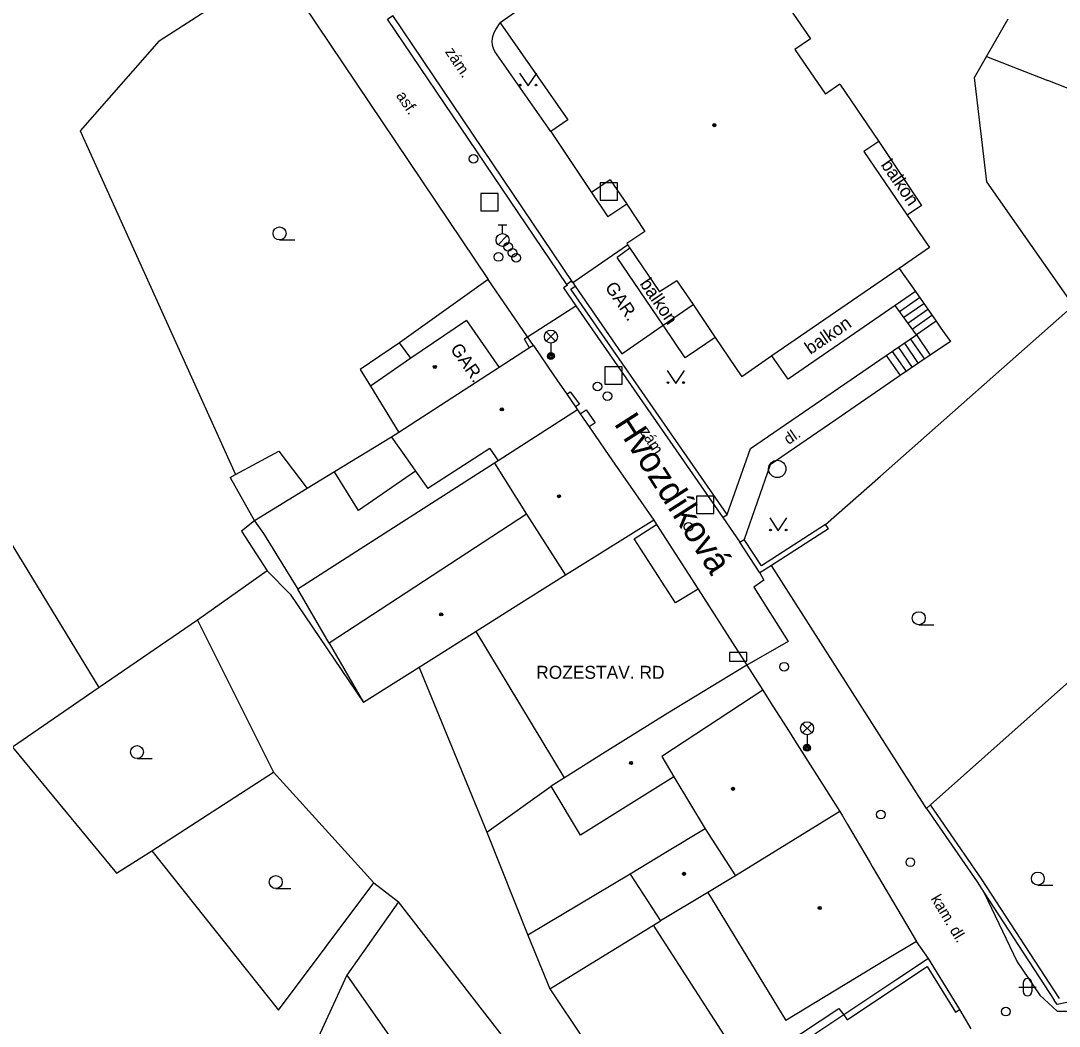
# Model space of a CAD drawing. Extents: x -598233 to -596890, y -1157848 to -1156431.
# Drawn here: x -597463.2 to -597403.3, y -1157373.5 to -1157315.5 of the extents above; entities that cross this region are included whole.
import ezdxf

# ---------------------------------------------------------------- set-up
doc = ezdxf.new("R2010")
doc.units = 0
for name, color, linetype in [('Level 11', 7, 'Continuous'), ('Level 24', 7, 'Continuous'), ('Level 26', 7, 'Continuous'), ('Level 27', 7, 'Continuous'), ('Level 28', 7, 'Continuous'), ('Level 33', 7, 'Continuous'), ('Level 36', 7, 'Continuous'), ('Level 39', 7, 'Continuous'), ('Level 40', 7, 'Continuous'), ('Level 41', 7, 'Continuous'), ('Level 42', 7, 'Continuous'), ('Level 5', 7, 'Continuous'), ('Level 50', 7, 'Continuous'), ('Level 7', 7, 'Continuous'), ('Level 8', 7, 'Continuous')]:
    doc.layers.add(name, color=color, linetype=linetype)

msp = doc.modelspace()

# ---------------------------------------------------------------- linework, layer by layer
at = {"layer": 'Level 11'}
for points in [[(-597431.38, -1157330.61), (-597441.77, -1157315.21)], [(-597407.49, -1157317.56), (-597406.25, -1157315.39)], [(-597432.64, -1157321.89), (-597435.88, -1157317.27), (-597435.95, -1157317.1), (-597436, -1157316.91), (-597436.02, -1157316.68), (-597435.99, -1157316.41), (-597435.92, -1157316.18), (-597435.82, -1157316), (-597435.57, -1157315.62)], [(-597455.25, -1157316.66), (-597459.82, -1157321.86), (-597450.85, -1157341.7)], [(-597407.48, -1157324.81), (-597408.18, -1157318.78), (-597407.49, -1157317.56)], [(-597407.49, -1157317.56), (-597403.95, -1157318.95)], [(-597458.72, -1157354), (-597478.57, -1157321.39), (-597481.79, -1157323.51), (-597492.54, -1157318.68), (-597503.21, -1157320.29), (-597510.41, -1157323.17)], [(-597394.15, -1157322.81), (-597403.95, -1157318.95)], [(-597413.7, -1157322.4699), (-597411.24, -1157326.1599), (-597412.07, -1157326.73)], [(-597402.48, -1157331.95), (-597407.48, -1157324.81)], [(-597430.3, -1157325.41), (-597429.35, -1157326.83)], [(-597428.26, -1157326.1), (-597429.35, -1157326.83)], [(-597428.08, -1157328.63), (-597428.81, -1157329.17)], [(-597426.15, -1157333.08), (-597428.81, -1157329.17)], [(-597412.54, -1157329.8), (-597411.6, -1157331.14)], [(-597436.26, -1157330.44), (-597441.37, -1157334.09)], [(-597411.6, -1157331.14), (-597412.76, -1157331.94)], [(-597412.52, -1157332.28), (-597411.36, -1157331.48)], [(-597411.6, -1157331.14), (-597410.4, -1157332.84)], [(-597433.99, -1157333.75), (-597431.19, -1157331.96)], [(-597426.15, -1157333.08), (-597424.43, -1157331.89)], [(-597412.76, -1157331.94), (-597418.95, -1157336.2), (-597419.88, -1157334.85)], [(-597411.54, -1157333.64), (-597412.76, -1157331.94)], [(-597412.27, -1157332.62), (-597411.12, -1157331.82)], [(-597412.03, -1157332.96), (-597410.88, -1157332.1599)], [(-597411.78, -1157333.3), (-597410.64, -1157332.5)], [(-597410.4, -1157332.84), (-597411.54, -1157333.64)], [(-597410.4, -1157332.84), (-597410.13, -1157333.24), (-597409.93, -1157333.52), (-597409.58, -1157334.01), (-597410.74, -1157334.81)], [(-597428.54, -1157334.73), (-597426.15, -1157333.08)], [(-597423.15, -1157333.79), (-597424.18, -1157334.49), (-597424.88, -1157334.96), (-597426.15, -1157333.08)], [(-597441.37, -1157334.09), (-597443.65, -1157335.64), (-597443.06, -1157336.6)], [(-597440.7199, -1157334.99), (-597441.37, -1157334.09)], [(-597413.28, -1157334.83), (-597411.54, -1157333.64)], [(-597412.23, -1157334.12), (-597411.43, -1157335.28)], [(-597411.88, -1157333.88), (-597411.08, -1157335.04)], [(-597411.54, -1157333.64), (-597410.74, -1157334.81)], [(-597412.93, -1157334.59), (-597412.12, -1157335.76)], [(-597412.58, -1157334.36), (-597411.78, -1157335.52)], [(-597422.47, -1157344), (-597421.11, -1157340.2), (-597413.28, -1157334.83)], [(-597413.28, -1157334.83), (-597412.4699, -1157335.99)], [(-597410.74, -1157334.81), (-597412.4699, -1157335.99)], [(-597412.4699, -1157335.99), (-597416.19, -1157338.54), (-597419.99, -1157341.14), (-597421.48, -1157345.45)], [(-597431.7199, -1157337.06), (-597431.52, -1157336.92), (-597430.99, -1157337.64), (-597431.21, -1157337.79)], [(-597430.94, -1157338.2), (-597430.61, -1157337.9699), (-597430.09, -1157338.7199), (-597430.43, -1157338.95)], [(-597441.84, -1157339.54), (-597445.13, -1157341.55), (-597446.7, -1157342.51)], [(-597451.15, -1157341.86), (-597450.85, -1157341.7), (-597448.34, -1157340.35), (-597446.7, -1157342.51)], [(-597435.9, -1157341.05), (-597444.39, -1157346.49)], [(-597451.15, -1157341.86), (-597449.74, -1157344.37)], [(-597440.45, -1157341.51), (-597443.75, -1157343.77), (-597445.13, -1157341.55)], [(-597446.7, -1157342.51), (-597449.74, -1157344.37)], [(-597449.74, -1157344.37), (-597450.49, -1157344.96), (-597449.02, -1157347.25)], [(-597449.74, -1157344.37), (-597449.2199, -1157345.11)], [(-597416.62, -1157344.84), (-597416.78, -1157344.58)], [(-597449.2199, -1157345.11), (-597447.24, -1157348.32)], [(-597444.39, -1157346.49), (-597447.24, -1157348.32)], [(-597449.02, -1157347.25), (-597453.04, -1157350.1)], [(-597449.02, -1157347.25), (-597447.69, -1157348.61)], [(-597420.57, -1157347.37), (-597420.34, -1157347.79), (-597420.92, -1157348.2)], [(-597445.44, -1157351.43), (-597447.24, -1157348.32)], [(-597420.92, -1157348.2), (-597418.95, -1157351.34), (-597421.33, -1157352.7)], [(-597447.69, -1157348.61), (-597443.46, -1157354.86)], [(-597453.04, -1157350.1), (-597458.72, -1157354), (-597463.71, -1157357.43), (-597457.7199, -1157364.71), (-597455.68, -1157363.4099)], [(-597453.04, -1157350.1), (-597448.65, -1157358.87)], [(-597431.86, -1157359.21), (-597436.96, -1157350.76)], [(-597455.68, -1157363.4099), (-597448.65, -1157358.87)], [(-597448.65, -1157358.87), (-597442.86, -1157365.27)], [(-597436.34, -1157362.34), (-597433.9699, -1157368.28)], [(-597455.68, -1157363.4099), (-597448.36, -1157372.62), (-597442.86, -1157365.27)], [(-597442.86, -1157365.27), (-597441.43, -1157366.36)], [(-597428.07, -1157364.76), (-597433.9699, -1157368.28)], [(-597407.62, -1157365.85), (-597405.72, -1157369.82), (-597404.41, -1157371.75), (-597403.42, -1157372.68), (-597402.25, -1157372.68), (-597401.32, -1157372.58), (-597400.2, -1157372.49), (-597398.82, -1157371.76)], [(-597441.43, -1157366.36), (-597444.4099, -1157370.59)], [(-597430.73, -1157380.1599), (-597441.43, -1157366.36)], [(-597426.7199, -1157367.71), (-597426.31, -1157367.46)], [(-597433.9699, -1157368.28), (-597432.7, -1157371.39)], [(-597432.7, -1157371.39), (-597426.7199, -1157367.71)], [(-597421.35, -1157376.04), (-597426.7199, -1157367.71)], [(-597444.4099, -1157370.59), (-597447.7, -1157377.75)], [(-597444.4099, -1157370.59), (-597435.63, -1157383.17)], [(-597432.7, -1157371.39), (-597426.76, -1157380.28)]]:
    msp.add_lwpolyline(points, dxfattribs=at)
at = {"layer": 'Level 24'}
for points in [[(-597433.99, -1157333.75), (-597434.17, -1157333.88)], [(-597433.87, -1157334.38), (-597434.17, -1157333.88)]]:
    msp.add_lwpolyline(points, dxfattribs=at)
msp.add_lwpolyline([(-597422.32, -1157352.47), (-597421.32, -1157352.47), (-597421.32, -1157351.97), (-597422.32, -1157351.97)], close=True, dxfattribs=at)
at = {"layer": 'Level 26'}
for points in [[(-597429.8, -1157325.86), (-597428.8, -1157325.86), (-597428.8, -1157324.86), (-597429.8, -1157324.86)], [(-597436.69, -1157326.48), (-597435.69, -1157326.48), (-597435.69, -1157325.48), (-597436.69, -1157325.48)], [(-597429.52, -1157336.48), (-597428.52, -1157336.48), (-597428.52, -1157335.48), (-597429.52, -1157335.48)], [(-597424.24, -1157343.95), (-597423.24, -1157343.95), (-597423.24, -1157342.95), (-597424.24, -1157342.95)]]:
    msp.add_lwpolyline(points, close=True, dxfattribs=at)
at = {"layer": 'Level 27'}
msp.add_circle((-597419.57, -1157341.37), 0.5, dxfattribs=at)
at = {"layer": 'Level 28'}
for p, q in [((-597435.68, -1157327.285), (-597435.18, -1157327.285)), ((-597435.43, -1157327.785), (-597435.43, -1157327.285)), ((-597435.688, -1157328.432), (-597435.158, -1157327.902))]:
    msp.add_line(p, q, dxfattribs=at)
for centre, radius in [((-597437.11, -1157323.47), 0.25), ((-597435.43, -1157328.16), 0.375), ((-597435.11, -1157328.55), 0.25), ((-597434.85, -1157328.9), 0.25), ((-597435.67, -1157329.14), 0.25), ((-597434.64, -1157329.19), 0.25), ((-597429.95, -1157336.62), 0.25), ((-597429.38, -1157337.18), 0.25), ((-597424.7, -1157344.72), 0.25), ((-597419.18, -1157352.79), 0.25), ((-597413.59, -1157361.33), 0.25), ((-597411.89, -1157364.08), 0.25), ((-597406.38, -1157372.7), 0.25)]:
    msp.add_circle(centre, radius, dxfattribs=at)
at = {"layer": 'Level 33'}
for p, q in [((-597432.905, -1157334), (-597432.375, -1157333.47)), ((-597432.905, -1157333.47), (-597432.375, -1157334)), ((-597432.64, -1157334.11), (-597432.64, -1157334.86)), ((-597418.115, -1157356.61), (-597417.585, -1157356.08)), ((-597418.115, -1157356.08), (-597417.585, -1157356.61)), ((-597417.85, -1157356.72), (-597417.85, -1157357.47))]:
    msp.add_line(p, q, dxfattribs=at)
for centre, radius in [((-597432.64, -1157333.735), 0.375), ((-597432.64, -1157334.86), 0.2), ((-597432.64, -1157334.86), 0.1445), ((-597432.64, -1157334.86), 0.0876), ((-597417.85, -1157356.345), 0.375), ((-597417.85, -1157357.47), 0.2), ((-597417.85, -1157357.47), 0.1445), ((-597417.85, -1157357.47), 0.0876)]:
    msp.add_circle(centre, radius, dxfattribs=at)
at = {"layer": 'Level 36'}
for p, q in [((-597448.3, -1157328.155), (-597447.425, -1157328.155)), ((-597411.4, -1157350.365), (-597410.525, -1157350.365)), ((-597456.53, -1157358.0949), (-597455.655, -1157358.0949)), ((-597448.52, -1157365.5949), (-597447.645, -1157365.5949)), ((-597404.53, -1157365.395), (-597403.655, -1157365.395)), ((-597405.626, -1157371.296), (-597404.626, -1157371.296)), ((-597405.376, -1157371.046), (-597405.376, -1157371.546)), ((-597404.876, -1157371.046), (-597404.876, -1157371.546))]:
    msp.add_line(p, q, dxfattribs=at)
for points in [[(-597434.45, -1157318.52), (-597433.95, -1157319.27), (-597433.45, -1157318.52)], [(-597425.93, -1157335.69), (-597425.43, -1157336.44), (-597424.93, -1157335.69)], [(-597420.01, -1157344.2), (-597419.51, -1157344.95), (-597419.01, -1157344.2)]]:
    msp.add_lwpolyline(points, dxfattribs=at)
for centre, radius in [((-597434.4002, -1157319.2198), 0.05), ((-597433.5008, -1157319.2198), 0.05), ((-597448.3001, -1157327.7799), 0.375), ((-597425.8802, -1157336.3898), 0.05), ((-597424.9808, -1157336.3898), 0.05), ((-597419.9602, -1157344.8998), 0.05), ((-597419.0608, -1157344.8998), 0.05), ((-597411.4001, -1157349.9899), 0.375), ((-597456.5301, -1157357.7198), 0.375), ((-597404.5301, -1157365.0199), 0.375), ((-597448.5201, -1157365.2198), 0.375)]:
    msp.add_circle(centre, radius, dxfattribs=at)
for centre, start, end in [((-597405.1257, -1157371.0463), 0, 180), ((-597405.1257, -1157371.5463), 180, 0)]:
    msp.add_arc(centre, 0.25, start, end, dxfattribs=at)
at = {"layer": 'Level 39'}
for centre, radius in [((-597423.21, -1157321.53), 0.09), ((-597423.21, -1157321.53), 0.0398), ((-597439.34, -1157335.49), 0.09), ((-597439.34, -1157335.49), 0.0398), ((-597435.4699, -1157337.94), 0.09), ((-597435.4699, -1157337.94), 0.0398), ((-597432.17, -1157342.95), 0.09), ((-597432.17, -1157342.95), 0.0398), ((-597438.9699, -1157349.77), 0.09), ((-597438.9699, -1157349.77), 0.0398), ((-597428.01, -1157358.35), 0.09), ((-597428.01, -1157358.35), 0.0398), ((-597422.13, -1157359.84), 0.09), ((-597422.13, -1157359.84), 0.0398), ((-597424.96, -1157364.75), 0.09), ((-597424.96, -1157364.75), 0.0398), ((-597417.12, -1157366.7199), 0.09), ((-597417.12, -1157366.7199), 0.0398)]:
    msp.add_circle(centre, radius, dxfattribs=at)
at = {"layer": 'Level 5'}
for points in [[(-597420.01, -1157313.12), (-597417.6599, -1157316.54)], [(-597433.82, -1157314.43), (-597434.48, -1157314.88), (-597435.57, -1157315.62)], [(-597435.57, -1157315.62), (-597431.6599, -1157321.23)], [(-597417.6599, -1157316.54), (-597418.56, -1157317.1599)], [(-597418.56, -1157317.1599), (-597416.79, -1157319.74)], [(-597415.96, -1157319.17), (-597416.79, -1157319.74)], [(-597415.96, -1157319.17), (-597413.7, -1157322.4699)], [(-597431.6599, -1157321.23), (-597432.64, -1157321.89)], [(-597432.64, -1157321.89), (-597430.3, -1157325.4099)], [(-597413.7, -1157322.4699), (-597414.57, -1157323.06)], [(-597414.57, -1157323.06), (-597412.07, -1157326.73)], [(-597429.21, -1157324.68), (-597430.3, -1157325.4099)], [(-597429.21, -1157324.68), (-597428.62, -1157325.56), (-597428.28, -1157326.06), (-597428.26, -1157326.1), (-597427.21, -1157327.67)], [(-597412.07, -1157326.73), (-597410.79, -1157328.6)], [(-597427.21, -1157327.67), (-597428.26, -1157328.37)], [(-597431.38, -1157330.61), (-597428.21, -1157328.44)], [(-597428.26, -1157328.37), (-597428.21, -1157328.44), (-597428.08, -1157328.63)], [(-597428.08, -1157328.63), (-597426.37, -1157331.15)], [(-597410.79, -1157328.6), (-597412.54, -1157329.8)], [(-597412.54, -1157329.8), (-597419.88, -1157334.85)], [(-597425.36, -1157330.51), (-597426.37, -1157331.15)], [(-597425.36, -1157330.51), (-597424.43, -1157331.89), (-597423.15, -1157333.79)], [(-597431.38, -1157330.61), (-597431.24, -1157330.82), (-597428.54, -1157334.73)], [(-597437.51, -1157332.8), (-597440.7199, -1157334.99)], [(-597437.51, -1157332.8), (-597435.63, -1157335.52)], [(-597423.15, -1157333.79), (-597421.62, -1157336.05)], [(-597433.65, -1157334.24), (-597433.87, -1157334.38), (-597435.63, -1157335.52)], [(-597433.65, -1157334.24), (-597432.46, -1157335.98), (-597432.12, -1157336.48), (-597431.76, -1157337), (-597431.7199, -1157337.06)], [(-597440.7199, -1157334.99), (-597443.06, -1157336.6)], [(-597419.88, -1157334.85), (-597421.62, -1157336.05)], [(-597435.63, -1157335.52), (-597441.42, -1157339.28)], [(-597443.06, -1157336.6), (-597441.42, -1157339.28)], [(-597431.7199, -1157337.06), (-597431.21, -1157337.79)], [(-597431.1, -1157337.96), (-597435.68, -1157340.9)], [(-597431.21, -1157337.79), (-597431.1, -1157337.96)], [(-597431.1, -1157337.96), (-597430.94, -1157338.2)], [(-597430.94, -1157338.2), (-597430.43, -1157338.95)], [(-597441.42, -1157339.28), (-597441.84, -1157339.54)], [(-597430.43, -1157338.95), (-597430.09, -1157339.44), (-597429.29, -1157340.6), (-597428.95, -1157341.09), (-597426.7, -1157344.34)], [(-597441.84, -1157339.54), (-597440.9, -1157340.87)], [(-597436.1599, -1157340.19), (-597439.74, -1157342.51)], [(-597436.1599, -1157340.19), (-597435.68, -1157340.9)], [(-597440.9, -1157340.87), (-597440.45, -1157341.51), (-597439.74, -1157342.51)], [(-597435.68, -1157340.9), (-597435.9, -1157341.05)], [(-597435.9, -1157341.05), (-597434.04, -1157343.98)], [(-597434.04, -1157343.98), (-597445.44, -1157351.43)], [(-597434.04, -1157343.98), (-597431.79, -1157347.51)], [(-597426.7, -1157344.34), (-597431.15, -1157347.11)], [(-597424.14, -1157348.32), (-597425.44, -1157349.11), (-597427.84, -1157345.4), (-597426.54, -1157344.59)], [(-597426.7, -1157344.34), (-597426.54, -1157344.59), (-597424.14, -1157348.32), (-597421.85, -1157351.89), (-597421.53, -1157352.39), (-597421.33, -1157352.7)], [(-597431.15, -1157347.11), (-597431.79, -1157347.51)], [(-597431.79, -1157347.51), (-597434.48, -1157349.2)], [(-597434.48, -1157349.2), (-597436.96, -1157350.76), (-597440.24, -1157352.83), (-597443.46, -1157354.86)], [(-597445.44, -1157351.43), (-597443.46, -1157354.86)], [(-597421.33, -1157352.7), (-597425.89, -1157355.4699)], [(-597421.33, -1157352.7), (-597420.41, -1157354.14)], [(-597440.24, -1157352.83), (-597436.34, -1157362.34)], [(-597420.41, -1157354.14), (-597426.23, -1157357.98)], [(-597420.41, -1157354.14), (-597420.15, -1157354.55), (-597419.83, -1157355.06), (-597418.89, -1157356.53), (-597418.57, -1157357.04), (-597415.96, -1157361.14)], [(-597425.89, -1157355.4699), (-597429.5, -1157357.73)], [(-597429.5, -1157357.73), (-597431.86, -1157359.21), (-597432.62, -1157359.68)], [(-597426.23, -1157357.98), (-597425.54, -1157359.14)], [(-597425.54, -1157359.14), (-597430.93, -1157362.51)], [(-597425.54, -1157359.14), (-597423.74, -1157362.15)], [(-597436.34, -1157362.34), (-597432.62, -1157359.68)], [(-597430.93, -1157362.51), (-597432.62, -1157359.68)], [(-597415.96, -1157361.14), (-597421.98, -1157364.86)], [(-597415.96, -1157361.14), (-597415.81, -1157361.39), (-597415.51, -1157361.9), (-597414.51, -1157363.6), (-597414.21, -1157364.11), (-597414.09, -1157364.32), (-597413.78, -1157364.84), (-597412.11, -1157367.67), (-597411.53, -1157368.66)], [(-597423.74, -1157362.15), (-597426, -1157363.51)], [(-597423.74, -1157362.15), (-597421.98, -1157364.86)], [(-597426, -1157363.51), (-597428.07, -1157364.76)], [(-597428.07, -1157364.76), (-597426.31, -1157367.46)], [(-597421.98, -1157364.86), (-597423.57, -1157365.82)], [(-597423.57, -1157365.82), (-597426.31, -1157367.46)], [(-597423.57, -1157365.82), (-597419.08, -1157373.2199)], [(-597411.53, -1157368.66), (-597413.3, -1157369.72), (-597419.08, -1157373.2199)]]:
    msp.add_lwpolyline(points, dxfattribs=at)
at = {"layer": 'Level 7'}
for points in [[(-597455.25, -1157316.66), (-597448.45, -1157312.27)], [(-597448.45, -1157312.27), (-597436.26, -1157330.44)], [(-597431.7199, -1157330.73), (-597442.07, -1157315.42), (-597441.77, -1157315.21)], [(-597431.7199, -1157330.73), (-597431.7, -1157330.78), (-597431.91, -1157330.92), (-597431.19, -1157331.96)], [(-597431.38, -1157330.61), (-597431.48, -1157330.56), (-597431.7199, -1157330.73)], [(-597422.47, -1157344), (-597431.49, -1157331), (-597431.24, -1157330.82)], [(-597431.19, -1157331.96), (-597422.72, -1157344.17), (-597422.47, -1157344)], [(-597416.78, -1157344.58), (-597413.62, -1157341.79), (-597402.48, -1157331.95)], [(-597433.65, -1157334.24), (-597433.99, -1157333.75)], [(-597416.62, -1157344.84), (-597419.9, -1157346.94), (-597420.57, -1157347.37), (-597421.73, -1157345.61), (-597421.48, -1157345.45)], [(-597416.78, -1157344.58), (-597420.48, -1157346.96), (-597421.48, -1157345.45)], [(-597410.95, -1157360.98), (-597419.9, -1157346.94)], [(-597401.31, -1157352.4), (-597410.73, -1157360.77)], [(-597410.73, -1157360.77), (-597410.95, -1157360.98)], [(-597410.95, -1157360.98), (-597408.04, -1157365.2), (-597407.62, -1157365.85), (-597406.51, -1157367.55)], [(-597403.28, -1157371.95), (-597407.79, -1157365.03), (-597410.73, -1157360.77)], [(-597406.51, -1157367.55), (-597403.59, -1157372.03)], [(-597410.85, -1157369.64), (-597412.67, -1157370.84), (-597415.7199, -1157372.88)], [(-597412.51, -1157371.15), (-597410.92, -1157370.09), (-597409.29, -1157372.74)], [(-597409.29, -1157372.74), (-597409.03, -1157372.58), (-597410.85, -1157369.64)], [(-597415.7199, -1157372.88), (-597415.53, -1157373.17), (-597412.51, -1157371.15)], [(-597400.37, -1157371.39), (-597400.29, -1157371.63), (-597403.42, -1157372.29), (-597403.59, -1157372.03)], [(-597421.35, -1157376.04), (-597416.02, -1157372.52), (-597415.7199, -1157372.88)], [(-597415.7199, -1157372.88), (-597419.95, -1157375.7)]]:
    msp.add_lwpolyline(points, dxfattribs=at)
at = {"layer": 'Level 8'}
for points in [[(-597433.99, -1157333.75), (-597436.26, -1157330.44)], [(-597422.72, -1157344.17), (-597421.73, -1157345.61)], [(-597410.85, -1157369.64), (-597411.53, -1157368.66)], [(-597408.38, -1157373.7), (-597409.03, -1157372.58)]]:
    msp.add_lwpolyline(points, dxfattribs=at)

# ---------------------------------------------------------------- texts
at = {"layer": 'Level 40'}
for s, rotation, p in [('zám.', 304.011658, (-597438.77, -1157317.3)), ('asf.', 304.011658, (-597441.6, -1157319.83)), ('zám.', 302.714436, (-597427.53, -1157339.22)), ('dl.', 34.40492, (-597418.92, -1157340)), ('kam. dl.', 301, (-597410.73, -1157366.18))]:
    msp.add_text(s, height=0.65, rotation=rotation, dxfattribs=at).set_placement(p)
at = {"layer": 'Level 41'}
for rotation, p in [(304.527972, (-597429.55, -1157330.89)), (305, (-597438.48, -1157334.45))]:
    msp.add_text('GAR.', height=0.75, rotation=rotation, dxfattribs=at).set_placement(p)
msp.add_text('ROZESTAV. RD', height=0.75, dxfattribs=at).set_placement((-597433.49, -1157353.49))
at = {"layer": 'Level 42'}
for rotation, p in [(304.359992, (-597413.62, -1157323.82)), (304.359992, (-597427.54, -1157330.68)), (34.419981, (-597417.66, -1157334.8))]:
    msp.add_text('balkon', height=0.75, rotation=rotation, dxfattribs=at).set_placement(p)
at = {"layer": 'Level 50'}
msp.add_text('Hvozdíková', height=1.5, rotation=302.704253, dxfattribs=at).set_placement((-597429.0295, -1157338.7646))

doc.saveas('drawing.dxf')
